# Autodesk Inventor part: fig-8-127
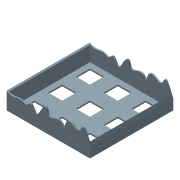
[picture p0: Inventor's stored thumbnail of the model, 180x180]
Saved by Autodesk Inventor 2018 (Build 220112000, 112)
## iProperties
Shininess: 64.0
Length Units: 11269
Angle Units: 11279
Time Units: 11290
Mass Units: 11283
Length Display Precision: 3
Angle Display Precision: 2
Compacted: True
Part Number: fig-8-127
Document SubType Name: Modeling
Created: 2002-12
Designer: deepak
Density: 1 g/cm^3
Material: Generic
Appearance: Light Steel Blue
Density: 0.0
Volumn: 0.0
Area: 0.0
PropertySet Name: Model Information
Control State: 0
Master: False
Checked Out: False
Author: deepak
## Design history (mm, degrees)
sketch "Sketch1"
  geometry: L1 (-32.188, 30.089)-(27.812, 30.089); L2 (27.812, 30.089)-(27.812, -29.911); L3 (27.812, -29.911)-(-32.188, -29.911); L4 (-32.188, -29.911)-(-32.188, 30.089)
  constraints: 8 end point, 2 parallel, 1 horizontal, 1 perpendicular
  dimensions: "d0" = 60 distance of L1.start L1.end; "d1" = 60 distance of L3.end L1.start
extrude "Extrusion1" new body sketch "Sketch1" stored distance "d2" = 20; taper "d3" = 0 deg
shell "Shell2" dims "d21" = 1
sketch "Sketch5"
  geometry: L1 (-27.812, 30.089)-(32.188, 30.089) reference; L2 (-27.812, -29.911)-(-27.812, 30.089) reference; L3 (-22.812, 25.089)-(-12.812, 25.089); L4 (-12.812, 25.089)-(-12.812, 15.089); L5 (-12.812, 15.089)-(-22.812, 15.089); L6 (-22.812, 15.089)-(-22.812, 25.089)
  constraints: 8 end point, 2 parallel, 1 horizontal, 1 perpendicular
  dimensions: "d8" = 10 distance of L3.start L3.end; "d9" = 10 distance of L5.end L3.start; "d10" = 5 distance between parallel lines of L2 L6; "d11" = 5 distance between parallel lines of L1 L3
extrude "Extrusion2" cut sketch "Sketch5" distance "d12" = 50; taper "d13" = 0 deg
pattern_linear "Rectangular Pattern1" dims "d16" = 20, "d19" = 20
sketch "Sketch2"
  geometry: 17 further points
  constraints: 17 other
extrude_surface "ExtrusionSrf1" sketch "Sketch2" dims "d4" = 70, "d5" = 0
split "Split2"
body "Solid1"
body "Srf1"
